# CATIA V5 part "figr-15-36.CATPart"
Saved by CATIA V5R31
Part number: Part1
Bounding box of the stored display mesh (mm): x -63.331 to 107.433, y -39.139 to 39.139, z 0 to 70.926
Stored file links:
  D:\PROJECTS\Project 2021\US EDITION\CATIA V5 6R 2021\Resources\Part Files\c15_catia_v5_6r2021_prt\figr-15-36.CATPart
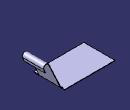
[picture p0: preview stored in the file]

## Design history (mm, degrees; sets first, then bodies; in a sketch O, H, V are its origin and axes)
SheetMetalParameters1: Thickness 1, BendRadius 2, KFactor 0.400515 {= log(min(100,max(20*SheetMetalParameters1.BendRadius,SheetMetalParameters1.Thickness)/SheetMetalParameters1.Thickness))/log(100)/2}, ReliefRadialLength 1, ReliefAxialLength 2, MinimumBendRadius 0
Body1 (main body)
  Sketch1 on xy-plane, origin (0, 0, 0), H (1, 0, 0), V (0, 1, 0)
    line L1 (-63.3311, 39.1393) -> (63.3311, 39.1393)
    line L2 (63.3311, 39.1393) -> (63.3311, -39.1393)
    line L3 (63.3311, -39.1393) -> (-63.3311, -39.1393)
    line L4 (-63.3311, -39.1393) -> (-63.3311, 39.1393)
    horizontal: L1 H, L3 H
    vertical: L2 V, L4 V
    symmetry: L4 L2 V, L1 L3 H
  Wall1: Thickness 1, Profile Sketch1
  d_NewWallOnEdge1: NewWallOnEdge_Edge edge [face of Wall1 | face of Wall1], NewWallOnEdge_Length 67, NewWallOnEdge_HeightLimitOffset 0, NewWallOnEdge_WidthOffset1 -16, NewWallOnEdge_WidthOffset2 -9, NewWallOnEdge_Angle 115, NewWallOnEdge_BendRadiusValue 2 {= SheetMetalParameters1.BendRadius}, NewWallOnEdge_BendTable SheetMetalParameters1, KFacteur 0.400515 {= log(min(100,max(20*d_NewWallOnEdge1.Radius,SheetMetalParameters1.Thickness)/SheetMetalParameters1.Thickness))/log(100)/2}
  Flange1: Angle 4, Length 10, Radius 6, KFacteur 0.5 {= log(min(100,max(20*Flange1.Radius,SheetMetalParameters1.Thickness)/SheetMetalParameters1.Thickness))/log(100)/2}, Guide edge [face of d_NewWallOnEdge1 | face of d_NewWallOnEdge1]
